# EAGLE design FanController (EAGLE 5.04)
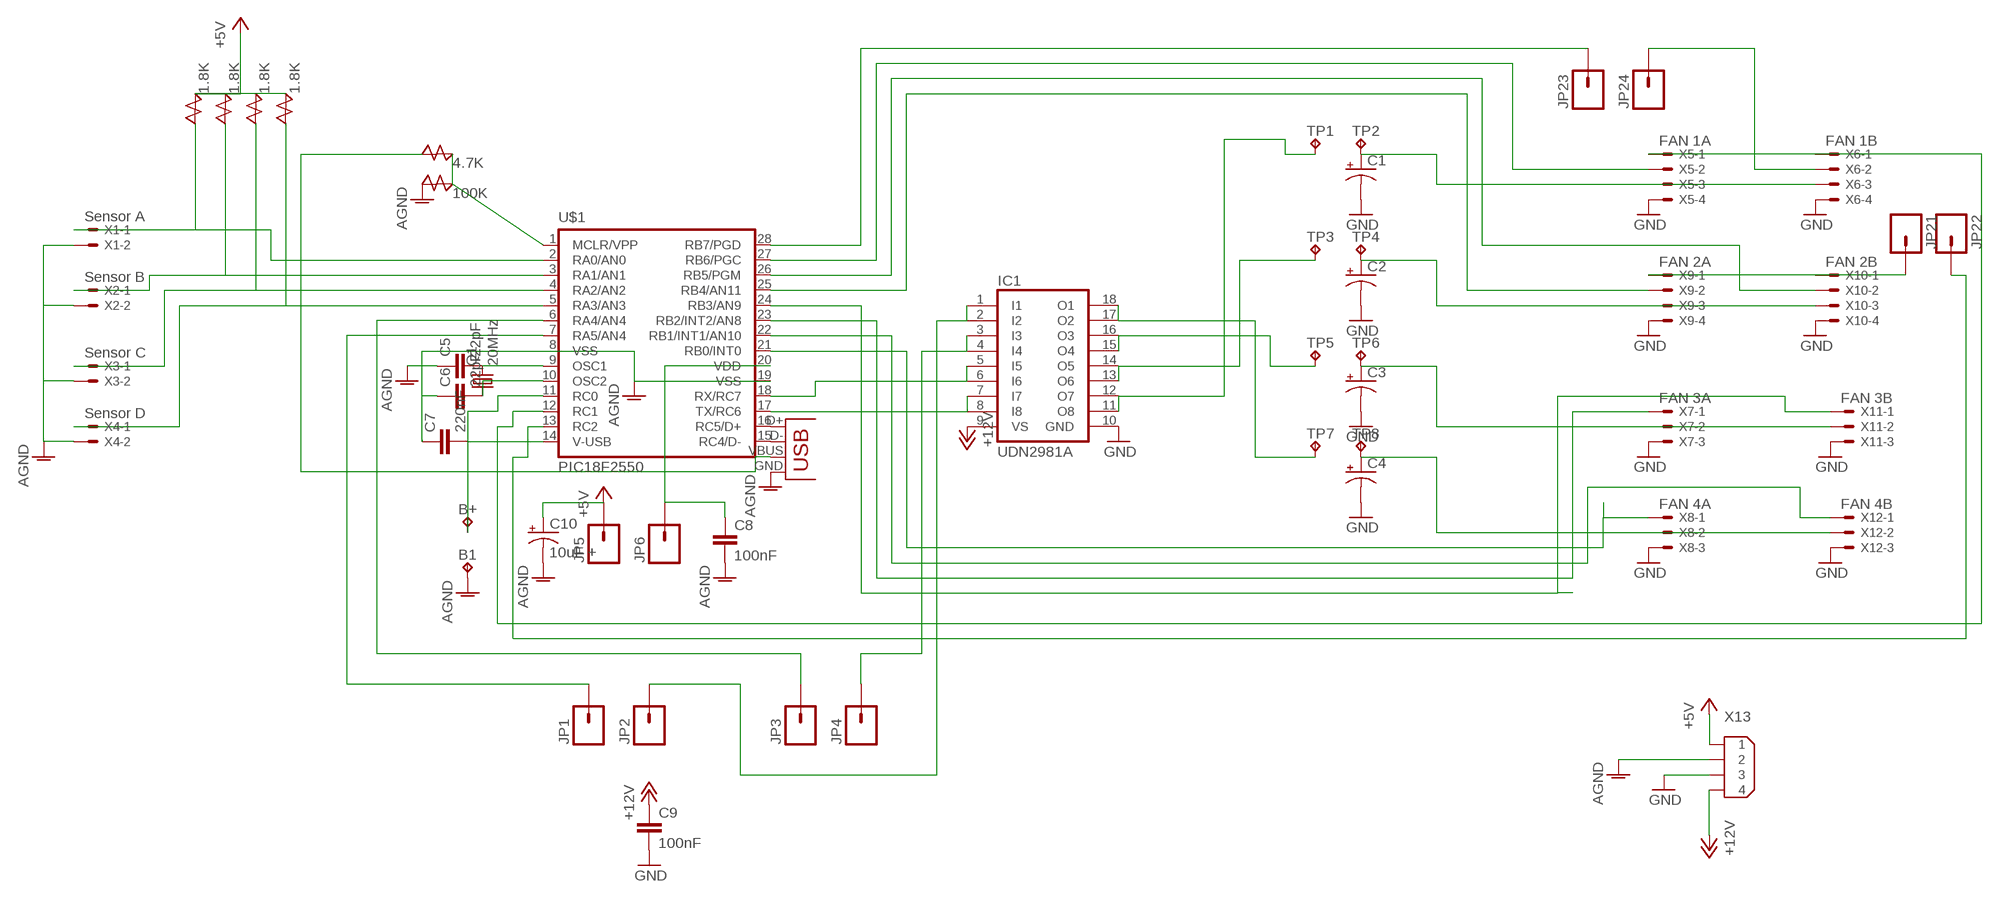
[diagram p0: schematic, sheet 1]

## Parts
B1  TPPAD1-13Y  [P1-13Y]
B+  BUZZER  TPPAD1-13Y  [P1-13Y]
C1  CPOL-USE5-10.5  [E5-10,5]
C2  CPOL-USE5-10.5  [E5-10,5]
C3  CPOL-USE5-10.5  [E5-10,5]
C4  CPOL-USE5-10.5  [E5-10,5]
C5  22pF  C5/3.5  [C5B3.5]
C6  22pF  C5/3.5  [C5B3.5]
C7  220nF  C5/3.5  [C5B3.5]
C8  100nF  C5/3.5  [C5B3.5]
C9  100nF  C5/3.5  [C5B3.5]
C10  10uF +  CPOL-USB45181B  [B45181B]
D1  1.8K  1N4148DO35-10  [DO35-10]
D2  1.8K  1N4148DO35-10  [DO35-10]
D3  1.8K  1N4148DO35-10  [DO35-10]
D4  1.8K  1N4148DO35-10  [DO35-10]
D5  100K  1N4148DO35-10  [DO35-10]
D6  4.7K  1N4148DO35-10  [DO35-10]
IC1  UDN2981A  [DIL18]
JP1  M01PTH_LONGPAD  [1X01_LONGPAD]
JP2  M01PTH_LONGPAD  [1X01_LONGPAD]
JP3  M01PTH_LONGPAD  [1X01_LONGPAD]
JP4  M01PTH_LONGPAD  [1X01_LONGPAD]
JP5  M01PTH_LONGPAD  [1X01_LONGPAD]
JP6  M01PTH_LONGPAD  [1X01_LONGPAD]
JP21  M01PTH_LONGPAD  [1X01_LONGPAD]
JP22  M01PTH_LONGPAD  [1X01_LONGPAD]
JP23  M01PTH_LONGPAD  [1X01_LONGPAD]
JP24  M01PTH_LONGPAD  [1X01_LONGPAD]
Q1  20MHz  CRYSTALHC49UV  [HC49U-V]
TP1  TPPAD1-13Y  [P1-13Y]
TP2  TPPAD1-13Y  [P1-13Y]
TP3  TPPAD1-13Y  [P1-13Y]
TP4  TPPAD1-13Y  [P1-13Y]
TP5  TPPAD1-13Y  [P1-13Y]
TP6  TPPAD1-13Y  [P1-13Y]
TP7  TPPAD1-13Y  [P1-13Y]
TP8  TPPAD1-13Y  [P1-13Y]
U$1  PIC18F2550  [DIL28-3]
X1  Sensor A  22-23-2021  [22-23-2021]
X2  Sensor B  22-23-2021  [22-23-2021]
X3  Sensor C  22-23-2021  [22-23-2021]
X4  Sensor D  22-23-2021  [22-23-2021]
X5  FAN 1A  22-23-2041  [22-23-2041]
X6  FAN 1B  22-23-2041  [22-23-2041]
X7  FAN 3A  22-23-2031  [22-23-2031]
X8  FAN 4A  22-23-2031  [22-23-2031]
X9  FAN 2A  22-23-2041  [22-23-2041]
X10  FAN 2B  22-23-2041  [22-23-2041]
X11  FAN 3B  22-23-2031  [22-23-2031]
X12  FAN 4B  22-23-2031  [22-23-2031]
X13  9090-4V  [9090-4V]
X17  USBPTH  [USB-B-PTH]

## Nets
+5V: C10.+ D1.C D2.C D3.C D4.C JP5.1 X13.1
+12V: C9.1 IC1.9(VS) X13.4
AGND: B1.1(TP) C5.1 C6.1 C7.1 C8.2 C10.- D5.A U$1.8(VSS) U$1.19(VSS) X1.2 X2.2 X3.2 X4.2 X13.2 X17.GND
GND: C1.- C2.- C3.- C4.- C9.2 IC1.10(GND) X5.4 X6.4 X7.3 X8.3 X9.4 X10.4 X11.3 X12.3 X13.3
N$1: U$1.21(RB0/INT0) X8.1
N$3: C6.2 Q1.1 U$1.10(OSC2)
N$4: D5.C D6.C U$1.1(MCLR/VPP)
N$5: U$1.16(RC5/D+) X17.D+
N$6: U$1.15(RC4/D-) X17.D-
N$7: D6.A X17.VBUS
N$8: C7.2 U$1.14(V-USB)
N$9: B+.1(TP) U$1.11(RC0)
N$10: U$1.22(RB1/INT1/AN10) X12.1
N$11: U$1.23(RB2/INT2/AN8) X7.1
N$12: U$1.24(RB3/AN9) X11.1
N$13: D1.A U$1.2(RA0/AN0) X1.1
N$14: D2.A U$1.3(RA1/AN1) X2.1
N$15: D3.A U$1.4(RA2/AN2) X3.1
N$16: D4.A U$1.5(RA3/AN3) X4.1
N$17: IC1.5(I5) IC1.6(I6) U$1.18(RX/RC7)
N$18: IC1.7(I7) IC1.8(I8) U$1.17(TX/RC6)
N$20: U$1.25(RB4/AN11) X9.2
N$21: IC1.11(O8) IC1.12(O7) TP1.1(TP)
N$22: C4.+ TP8.1(TP) X8.2 X12.2
N$23: IC1.15(O4) IC1.16(O3) TP5.1(TP)
N$24: IC1.13(O6) IC1.14(O5) TP3.1(TP)
N$25: IC1.3(I3) IC1.4(I4) JP4.1
N$26: C1.+ TP2.1(TP) X5.3 X6.3
N$27: C2.+ TP4.1(TP) X9.3 X10.3
N$28: C3.+ TP6.1(TP) X7.2 X11.2
N$29: U$1.26(RB5/PGM) X10.2
N$30: U$1.27(RB6/PGC) X5.2
N$31: IC1.17(O2) IC1.18(O1) TP7.1(TP)
N$32: JP3.1 U$1.6(RA4/AN4)
N$33: U$1.12(RC1) X5.1 X6.1
N$34: JP22.1 U$1.13(RC2)
N$35: JP1.1 U$1.7(RA5/AN4)
N$36: JP23.1 U$1.28(RB7/PGD)
N$37: IC1.1(I1) IC1.2(I2) JP2.1
N$38: C8.1 JP6.1 U$1.20(VDD)
N$39: C5.2 Q1.2 U$1.9(OSC1)
N$40: JP24.1 X6.2
N$41: JP21.1 X9.1 X10.1

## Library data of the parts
B1 B+ TP1-TP8 = testpad:TP: Test pad
C1-C4 = rcl:CPOL-US: POLARIZED CAPACITOR, American symbol
C5-C9 = capacitor-wima:C: CAPACITOR
C10 = resistor:CPOL-US: POLARIZED CAPACITOR, American symbol
D1-D6 = Geoff:1N4148: Resistor (Geoff's)
IC1 = uln-udn:UDN298*: DRIVER ARRAY Source: Allegro Microsystems Inc. / UDN2981-UDN2984.pdf
JP1-JP6 JP21-JP24 = SparkFun:M01: Header 1
Q1 = SparkFun:CRYSTAL: Crystals
U$1 = SparkFun:PIC18F2550
X1-X4 = con-molex:22-23-2021: .100" (2.54mm) Center Header - 2 Pin
X5 X6 X9 X10 = con-molex:22-23-2041: .100" (2.54mm) Center Header - 4 Pin
X7 X8 X11 X12 = con-molex:22-23-2031: .100" (2.54mm) Center Header - 3 Pin
X13 = con-thomas-betts:9090-4: Disk Drive Power four position Source: Thomas & Betts Electronic Interconnects Eiropean Edition 1998
X17 = SparkFun:USB: USB Connectors USB-B-PTH is fully proven SKU : PRT-00139 USB-miniB is fully proven SKU : PRT-00587 USB-A-PCB is untested. USB-A-H is throughly reviewed, but untested. Spark Fun Electronics SKU : PRT-00437 USB-B-SMT is throughly reviewed, but untested. Needs silkscreen touching up. USB-A-S has not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

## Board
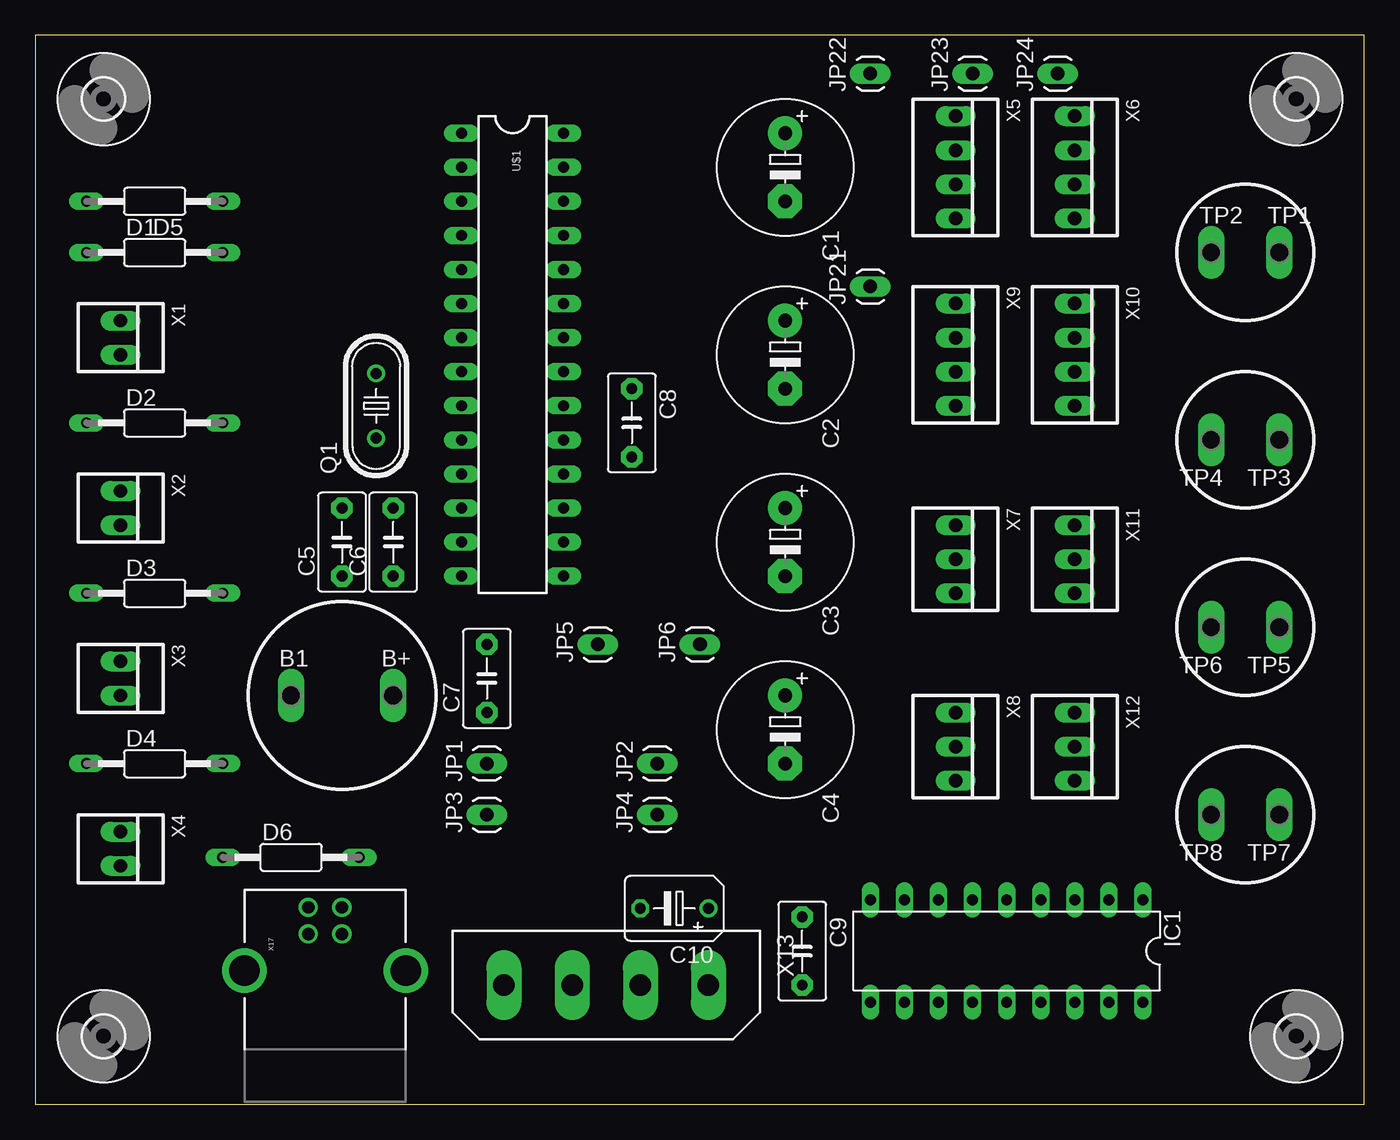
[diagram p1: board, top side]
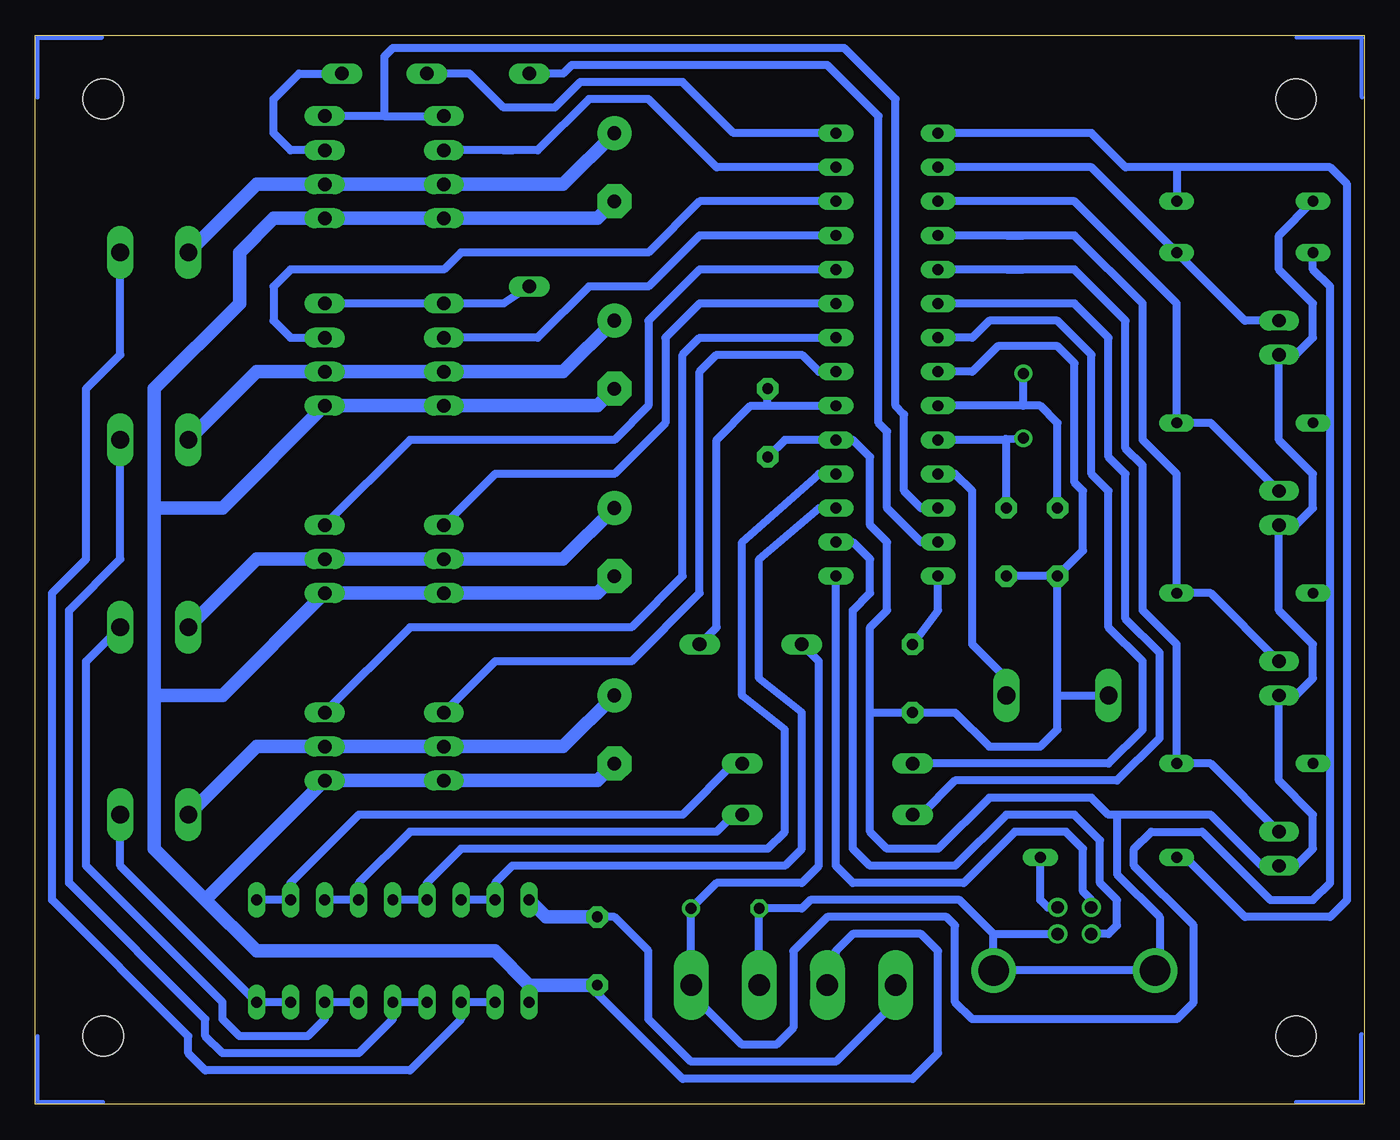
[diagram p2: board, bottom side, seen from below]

Size 99.04 x 79.68 mm. Coordinates in mm from the lower left corner, seen from the top.
Outline: 0,0 99.04,0 99.04,79.68 0,79.68 0,0
Copper layers (1*16): Top 0.035mm / dielectric 1.5mm / Bottom 0.035mm
Design rules "default *": minimum track width 24mil, minimum drill 24mil, track to track 25mil, track to pad 25mil, pad to pad 8mil, via to via 8mil, smd to smd 8mil, copper to edge 25mil, drill to drill 8mil, minimum pad ring 10mil, minimum via ring 8mil, stop-mask expansion 4mil, vias tented up to drill 0mil, thermal gap 10mil

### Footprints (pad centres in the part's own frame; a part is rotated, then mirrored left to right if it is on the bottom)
P1-13Y = drill 1.321 pad 1.905 long: 1 0,0
E5-10,5 = drill 1.016 pad 2.54 round: + -2.54,0 | drill 1.016 pad 2.54 octagon: - 2.54,0
C5B3.5 = drill 0.813 pad 1.6 octagon: 1 -2.54,0; 2 2.54,0
B45181B = drill 0.813 round: + -2.54,0 | drill 0.813 octagon: - 2.54,0
DO35-10 = drill 0.813 long: A 5.08,0; C -5.08,0
DIL18 = drill 0.813 long: 1 -10.16,-3.81; 2 -7.62,-3.81; 3 -5.08,-3.81; 4 -2.54,-3.81; 5 0,-3.81; 6 2.54,-3.81; 7 5.08,-3.81; 8 7.62,-3.81; 9 10.16,-3.81; 10 10.16,3.81; 11 7.62,3.81; 12 5.08,3.81; 13 2.54,3.81; 14 0,3.81; 15 -2.54,3.81; 16 -5.08,3.81; 17 -7.62,3.81; 18 -10.16,3.81
1X01_LONGPAD = drill 1.016 long: 1 0,0
HC49U-V = drill 0.813 round: 1 -2.413,0; 2 2.413,0
DIL28-3 = drill 0.813 long: 1 -13.97,-3.81; 2 -11.43,-3.81; 3 -8.89,-3.81; 4 -6.35,-3.81; 5 -3.81,-3.81; 6 -1.27,-3.81; 7 1.27,-3.81; 8 3.81,-3.81; 9 6.35,-3.81; 10 8.89,-3.81; 11 11.43,-3.81; 12 13.97,-3.81; 13 16.51,-3.81; 14 19.05,-3.81; 15 19.05,3.81; 16 16.51,3.81; 17 13.97,3.81; 18 11.43,3.81; 19 8.89,3.81; 20 6.35,3.81; 21 3.81,3.81; 22 1.27,3.81; 23 -1.27,3.81; 24 -3.81,3.81; 25 -6.35,3.81; 26 -8.89,3.81; 27 -11.43,3.81; 28 -13.97,3.81
3,0 = hole 3: 0,0
22-23-2021 = drill 1 long: 1 -1.27,0; 2 1.27,0
22-23-2041 = drill 1 long: 1 -3.81,0; 2 -1.27,0; 3 1.27,0; 4 3.81,0
22-23-2031 = drill 1 long: 1 -2.54,0; 2 0,0; 3 2.54,0
9090-4V = drill 1.6 pad 2.6 long: 1 -7.62,0; 2 -2.54,0; 3 2.54,0; 4 7.62,0
USB-B-PTH = drill 0.914 round: D+ 0,1.25; D- 1.981,1.25; GND 0,-1.25; VBUS 1.981,-1.25 | drill 2.286 round: P$1 -2.718,-6.02; P$2 -2.718,6.02

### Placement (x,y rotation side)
B1  19.05,30.48 0 top
B+  26.67,30.48 0 top
C1  55.88,69.85 270 top
C2  55.88,55.88 270 top
C3  55.88,41.91 270 top
C4  55.88,27.94 270 top
C5  22.86,41.91 90 top
C6  26.67,41.91 90 top
C7  33.66,31.75 90 top
C8  44.45,50.8 270 top
C9  57.15,11.43 270 top
C10  47.62,14.61 180 top
D1  8.89,63.5 0 top
D2  8.89,50.8 0 top
D3  8.89,38.1 0 top
D4  8.89,25.4 0 top
D5  8.89,67.31 180 top
D6  19.05,18.41 0 top
IC1  72.39,11.43 180 top
JP1  33.66,25.4 90 top
JP2  46.35,25.4 90 top
JP3  33.66,21.59 90 top
JP4  46.35,21.59 90 top
JP5  41.91,34.29 90 top
JP6  49.53,34.29 90 top
JP21  62.23,60.96 90 top
JP22  62.23,76.83 90 top
JP23  69.85,76.83 90 top
JP24  76.2,76.83 90 top
Q1  25.4,52.07 90 top
TP1  92.71,63.5 0 top
TP2  87.63,63.5 0 top
TP3  92.71,49.53 180 top
TP4  87.63,49.53 180 top
TP5  92.71,35.56 180 top
TP6  87.63,35.56 180 top
TP7  92.71,21.59 180 top
TP8  87.63,21.59 180 top
U$1  35.56,58.42 270 top
U$2  [3,0]  93.98,74.93 0 top
U$3  [3,0]  5.08,74.93 0 top
U$4  [3,0]  5.08,5.08 0 top
U$5  [3,0]  93.98,5.08 0 top
X1  6.35,57.15 270 top
X2  6.35,44.45 270 top
X3  6.35,31.75 270 top
X4  6.35,19.05 270 top
X5  68.58,69.85 270 top
X6  77.47,69.85 270 top
X7  68.58,40.64 270 top
X8  68.58,26.67 270 top
X9  68.58,55.88 270 top
X10  77.47,55.88 270 top
X11  77.47,40.64 270 top
X12  77.47,26.67 270 top
X13  42.55,8.89 180 top
X17  21.59,12.7 90 top

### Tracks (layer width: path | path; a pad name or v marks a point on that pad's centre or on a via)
+5V
  Bottom 0.61: 2.54,25.4 D4.C | 2.54,25.4 2.54,38.1 | 2.54,38.1 2.54,50.8 | 2.54,50.8 D2.C | 2.54,38.1 D3.C | D1.C 3.81,62.23 2.54,60.96 2.54,50.8 | 2.54,25.4 2.54,16.51 3.81,15.24 6.99,15.24 12.06,20.32 15.88,20.32 17.14,19.05 17.14,17.78 12.7,13.34 12.7,7.62 13.97,6.35 29.21,6.35 30.48,7.62 30.48,13.34 31.11,13.97 40.01,13.97 42.55,11.43 42.55,5.71 43.81,4.45 46.35,4.45 49.53,7.62 49.53,8.26 X13.1 | JP5.1 40.64,33.02 40.64,17.78 41.91,16.51 48.26,16.51 C10.+ | X13.1 C10.+ | X13.1 C10.+
+12V
  Bottom 0.61: C9.1 55.88,13.97 53.34,11.43 53.34,6.35 50.16,3.17 39.37,3.17 34.92,7.62 X13.4
  Bottom 1.016: C9.1 60.96,13.97 IC1.9
AGND
  Bottom 0.61: C8.2 43.18,49.53 U$1.19 38.1,49.53 36.83,48.26 36.83,43.18 35.56,41.91 35.56,36.83 36.83,35.56 36.83,29.21 | D5.A 6.35,64.77 6.35,62.23 3.81,59.69 3.81,57.15 5.08,55.88 X1.2 6.35,49.53 3.81,46.99 3.81,44.45 5.08,43.18 X2.2 6.35,36.83 3.81,34.29 3.81,31.75 5.08,30.48 X3.2 6.35,24.13 3.81,21.59 3.81,19.05 5.08,17.78 X4.2 7.62,17.78 11.43,21.59 18.41,21.59 | 27.62,12.7 X17.GND | 27.62,12.7 27.62,10.16 27.46,10 15.4,10 15.24,10.16 15.24,13.97 18.41,17.14 18.41,21.59 | 36.83,29.21 36.83,20.32 35.56,19.05 31.75,19.05 27.94,22.86 20.32,22.86 19.05,21.59 18.41,21.59 | 36.83,29.21 C7.1 30.48,29.21 27.94,26.67 24.13,26.67 22.86,27.94 22.86,30.48 | U$1.8 29.21,54.61 27.3,56.52 22.86,56.52 21.59,55.24 21.59,46.35 20.95,45.72 20.95,41.27 C5.1 | C5.1 C6.1 | 22.86,30.48 C5.1 | 22.86,30.48 B1.1 | X13.2 C10.- 41.91,14.61 41.27,15.24 30.16,15.24 27.62,12.7
GND
  Bottom 0.61: X13.3 39.37,11.43 38.1,12.7 33.02,12.7 31.75,11.43 31.75,3.81 33.66,1.91 50.8,1.91 57.15,8.26 C9.2
  Bottom 1.016: C9.2 62.23,8.89 | 62.23,8.89 64.77,11.43 82.55,11.43 86.36,15.24 | 90.17,30.48 90.17,44.45 | 90.17,44.45 90.17,53.34 83.82,59.69 83.82,63.5 81.28,66.04 X6.4 | 62.23,8.89 IC1.10 | 86.36,15.24 90.17,19.05 90.17,30.48 | 86.36,15.24 X12.3 X8.3 57.15,24.13 C4.- | 90.17,30.48 85.09,30.48 X11.3 X7.3 57.15,38.1 C3.- | 90.17,44.45 85.09,44.45 X10.4 X9.4 57.15,52.07 C2.- | 60.96,66.04 X5.4 X6.4 | X6.4 60.96,66.04 | 60.96,66.04 57.15,66.04 C1.-
N$1
  Bottom 0.61: U$1.21 40.64,54.61 41.91,55.88 48.26,55.88 49.53,54.61 49.53,38.1 54.61,33.02 64.77,33.02 X8.1
N$2
  Bottom 0.305: 5.05,79.51 0.17,79.5 0.17,75.05
N$3
  Bottom 0.61: U$1.10 26.8,49.53 26.73,49.59 | 26.73,49.59 Q1.1 | C6.2 26.67,49.53 26.73,49.59
N$4
  Bottom 0.61: D6.C 13.34,18.41 8.89,13.97 2.54,13.97 1.27,15.24 1.27,68.58 2.54,69.85 13.97,69.85 | 13.97,69.85 D5.C | 13.97,69.85 17.78,69.85 20.32,72.39 U$1.1
N$5
  Bottom 0.61: U$1.16 38.1,41.91 36.83,40.64 36.83,38.1 38.1,36.83 38.1,19.05 36.83,17.78 30.48,17.78 26.67,21.59 21.59,21.59 19.68,19.68 19.68,16.51 18.41,15.24 18.41,13.34 19.05,12.7 X17.D+
N$6
  Bottom 0.61: X17.D- 20.34,15.26 20.95,15.88 20.95,19.05 22.23,20.32 26.04,20.32 29.84,16.51 38.1,16.51 39.37,17.78 U$1.15
N$7
  Bottom 0.61: D6.A 24.13,15.24 23.57,14.68 X17.VBUS
N$8
  Bottom 0.61: U$1.14 31.75,36.83 C7.2
N$9
  Bottom 0.61: U$1.11 30.48,46.99 29.21,45.72 29.21,34.29 26.67,31.75 B+.1
N$10
  Bottom 0.61: X12.1 71.12,35.56 54.61,35.56 50.8,39.37 50.8,55.88 49.53,57.15 U$1.22
N$11
  Bottom 0.61: U$1.23 49.53,59.69 52.07,57.15 52.07,50.8 55.88,46.99 64.77,46.99 X7.1
N$12
  Bottom 0.61: X11.1 71.12,49.53 55.88,49.53 53.34,52.07 53.34,58.42 49.53,62.23 U$1.24
N$13
  Bottom 0.61: X1.1 8.89,58.42 D1.A 20.32,69.85 U$1.2
N$14
  Bottom 0.61: U$1.3 21.59,67.31 13.97,59.69 D2.A 11.43,50.8 X2.1
N$15
  Bottom 0.61: 26.67,64.77 25.4,64.77 | 26.67,64.77 U$1.4 | 26.67,64.77 21.59,64.77 16.51,59.69 16.51,49.53 13.97,46.99 D3.A 11.43,38.1 X3.1
N$16
  Bottom 0.61: 26.67,62.23 25.4,62.23 | 26.67,62.23 U$1.5 | 26.67,62.23 21.59,62.23 17.78,58.42 17.78,48.9 16.51,47.62 16.51,36.83 13.97,34.29 D4.A 11.43,25.4 X4.1
N$17
  Bottom 0.61: U$1.18 40.64,46.99 46.35,41.91 46.35,30.48 43.18,27.94 43.18,20.32 44.45,19.05 67.31,19.05 69.85,16.51 IC1.6 IC1.5
N$18
  Bottom 0.61: U$1.17 40.64,44.45 45.09,40.64 45.09,31.75 41.91,29.21 41.91,19.05 43.18,17.78 63.5,17.78 64.77,16.51 IC1.8 IC1.7
N$19
  Bottom 0.61: 17.14,10 26.19,10
N$20
  Bottom 0.61: 67.31,57.15 X9.2 61.59,57.15 57.78,60.96 53.34,60.96 49.53,64.77 U$1.25
N$21
  Bottom 0.61: IC1.11 IC1.12 67.31,6.35 71.12,2.54 86.36,2.54 87.63,3.81 87.63,5.08 97.79,15.24 97.79,38.1 95.25,40.64 95.25,53.34 92.71,55.88 TP1.1
N$22
  Bottom 1.016: TP8.1 82.55,26.67 X12.2 X8.2 59.69,26.67 C4.+
N$23
  Bottom 0.61: IC1.15 IC1.16 77.47,6.35 78.74,5.08 83.82,5.08 85.09,6.35 85.09,7.62 95.25,17.78 95.25,33.02 TP5.1
N$24
  Bottom 0.61: IC1.13 IC1.14 72.39,6.35 74.93,3.81 85.09,3.81 86.36,5.08 86.36,6.35 96.52,16.51 96.52,36.83 92.71,40.64 TP3.1
N$25
  Bottom 0.61: IC1.3 IC1.4 74.93,16.51 71.12,20.32 48.26,20.32 46.99,21.59 JP4.1
N$26
  Bottom 1.016: TP2.1 82.55,68.58 X6.3 X5.3 59.69,68.58 C1.+
N$27
  Bottom 1.016: TP4.1 82.55,54.61 X10.3 X9.3 59.69,54.61 C2.+
N$28
  Bottom 1.016: TP6.1 82.55,40.64 X11.2 X7.2 59.69,40.64 C3.+
N$29
  Bottom 0.61: U$1.26 49.53,67.31 53.34,63.5 67.31,63.5 68.58,62.23 80.01,62.23 81.28,60.96 81.28,58.42 80.01,57.15 X10.2
N$30
  Bottom 0.61: 64.14,71.12 63.5,71.12 | 64.14,71.12 X5.2 | U$1.27 48.26,69.85 53.34,74.93 57.78,74.93 61.59,71.12 64.14,71.12
N$31
  Bottom 0.61: IC1.17 IC1.18 92.71,17.78 TP7.1
N$32
  Bottom 0.61: U$1.6 21.59,59.69 19.05,57.15 19.05,48.26 17.78,46.99 17.78,36.2 15.24,33.66 15.24,27.3 18.41,24.13 30.48,24.13 33.02,21.59 JP3.1
N$33
  Bottom 0.61: U$1.12 33.02,44.45 34.29,45.72 34.29,51.44 34.92,52.07 34.92,74.93 38.73,78.74 72.39,78.74 73.03,78.11 73.03,73.66 | 73.03,73.66 X5.1 | 73.03,73.66 X6.1
N$34
  Bottom 0.61: U$1.13 33.02,41.91 35.56,44.45 35.56,50.16 36.2,50.8 36.2,73.66 40.01,77.47 59.05,77.47 59.69,76.83 JP22.1
N$35
  Bottom 0.61: U$1.7 29.21,57.15 27.94,58.42 22.86,58.42 20.32,55.88 20.32,46.99 19.05,45.72 19.05,35.56 16.51,33.02 16.51,27.94 19.05,25.4 JP1.1
N$36
  Bottom 0.61: U$1.28 46.99,72.39 50.8,76.2 58.42,76.2 60.33,74.3 64.14,74.3 66.67,76.83 JP23.1
N$37
  Bottom 0.61: IC1.1 IC1.2 80.01,16.51 74.93,21.59 50.8,21.59 46.99,25.4 JP2.1
N$38
  Bottom 0.61: JP6.1 48.26,35.56 48.26,49.53 45.72,52.07 44.45,52.07 | 44.45,52.07 U$1.20 | 44.45,52.07 C8.1
N$39
  Bottom 0.61: 25.4,52.07 24.13,52.07 22.86,50.8 C5.2 | 25.4,52.07 U$1.9 | 25.4,52.07 Q1.2
N$40
  Bottom 0.61: X6.2 80.01,71.12 81.28,72.39 81.28,74.93 79.38,76.83 JP24.1
N$41
  Bottom 0.61: X10.1 X9.1 64.14,59.69 JP21.1
N$42
  Bottom 0.305: 94.07,79.51 98.86,79.5 98.86,75.06
N$43
  Bottom 0.305: 98.86,5.08 98.86,0.17 93.98,0.17
N$44
  Bottom 0.305: 5.08,0.17 0.2,0.17 0.2,5.25

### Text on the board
tValues: 1 | 470uF | FAN 1A | FAN 1B | 100uH | 470uF | FAN 2A | FAN 2B | PIC18F2550 | 100uH | 470uF | FAN 3A | FAN 3B | - + | 100uH | BUZZER | 470uF | FAN 4A | FAN 4B | 1 | 100uH | USB | 12V POWER 5V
